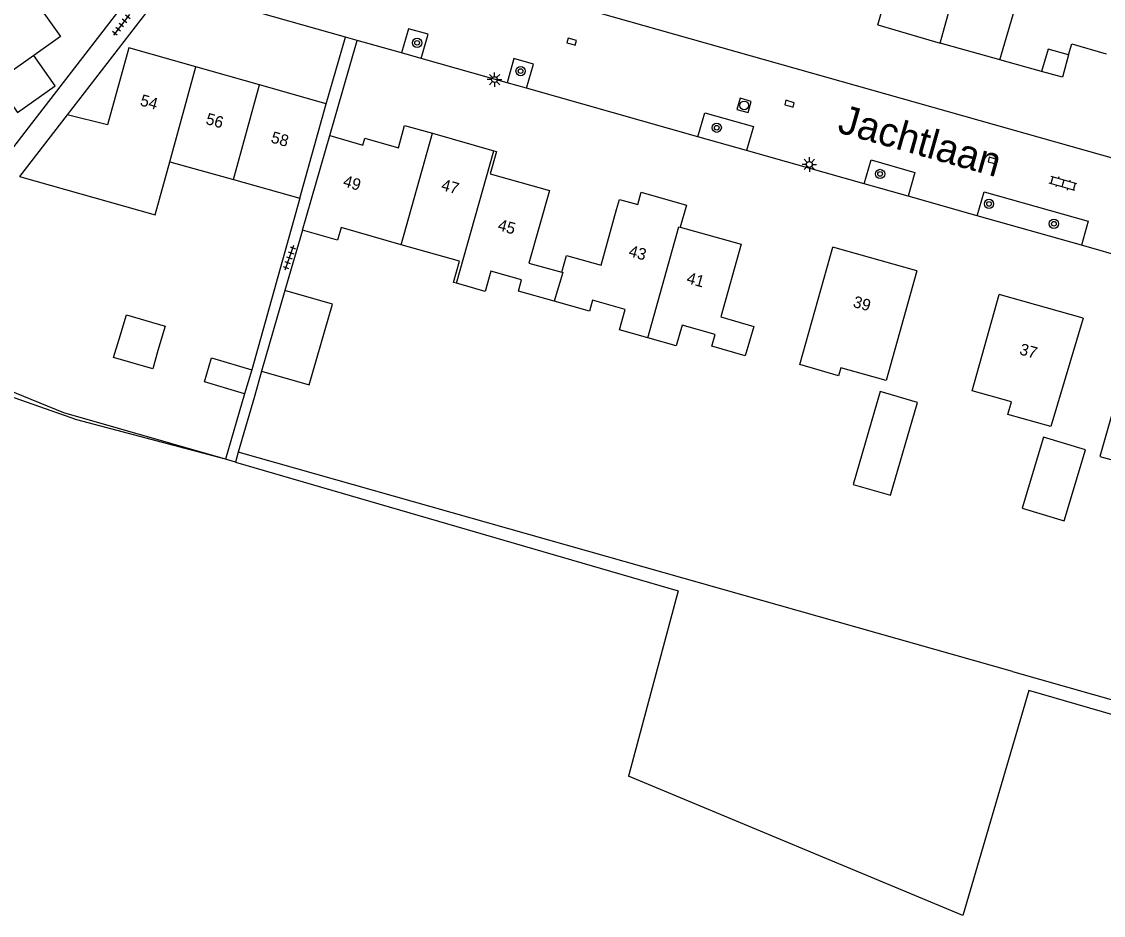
# Model space of a CAD drawing. Extents: x 136000 to 141000, y 400494 to 402006.
# Drawn here: x 137647.9 to 137741.1, y 401598.6 to 401675.6 of the extents above; entities that cross this region are included whole.
import ezdxf

# ---------------------------------------------------------------- set-up
doc = ezdxf.new("R2010")
doc.units = 0
for name, color, linetype in [('gg-afsc-draadraster', 7, 'Continuous'), ('gg-afsc-erfafscheiding', 7, 'Continuous'), ('gg-afsc-lijn draadraster', 7, 'Continuous'), ('gg-anno-huisnummerreeks BGT', 7, 'Continuous'), ('gg-anno-openbare ruimte label', 7, 'Continuous'), ('gg-bbg-gedigitaliseerde bebouwing', 7, 'Continuous'), ('gg-bbg-gedigitaliseerde bijgebouw', 7, 'Continuous'), ('gg-bbg-hoofdgebouw', 7, 'Continuous'), ('gg-bbg-luifel en loopbrug', 7, 'Continuous'), ('gg-bbg-tussenscheiding', 7, 'Continuous'), ('gg-knt-bronhoudergrens', 7, 'Continuous'), ('gg-knt-verharding', 7, 'Continuous'), ('gt-grn-groengrens', 7, 'Continuous'), ('gt-symb-boom', 7, 'Continuous'), ('gt-symb-klinker verharding', 7, 'Continuous'), ('gt-symb-kolk', 7, 'Continuous'), ('gt-symb-lichtmast', 7, 'Continuous'), ('gt-symb-rioolschacht', 7, 'Continuous'), ('gt-symb-tegel verharding', 7, 'Continuous')]:
    doc.layers.add(name, color=color, linetype=linetype)

# ---------------------------------------------------------------- blocks, each defined once
blk = doc.blocks.new('gt0-KOLK')
at = {"layer": 'gt-symb-kolk'}
blk.add_lwpolyline([(0, 0), (0.375, 0), (0.375, 0.4), (-0.375, 0.4), (-0.375, 0), (0, 0)], dxfattribs=at)
blk = doc.blocks.new('gt0-BOOM')
at = {"layer": 'gt-symb-boom'}
for radius in [0.4, 0.2]:
    blk.add_circle((0, 0), radius, dxfattribs=at)
blk = doc.blocks.new('gt0-TEG1')
at = {"layer": 'gt-symb-tegel verharding'}
for p, q in [((-1.125, 0), (1.125, 0)), ((-0.9, -0.25), (-0.9, 0.25)), ((-0.45, -0.25), (-0.45, 0.25)), ((0, -0.25), (0, 0.25)), ((0.45, -0.25), (0.45, 0.25)), ((0.9, -0.25), (0.9, 0.25))]:
    blk.add_line(p, q, dxfattribs=at)
blk = doc.blocks.new('gt0-KL1')
at = {"layer": 'gt-symb-klinker verharding'}
for p, q in [((-1.15, 0.3), (1.15, 0.3)), ((-1, -0.3), (-1, 0.3)), ((-0.5, 0.3), (-0.5, 0.45)), ((0, -0.3), (0, 0.3)), ((0.5, 0.3), (0.5, 0.45)), ((1, -0.3), (1, 0.3)), ((-1.15, -0.3), (1.15, -0.3)), ((-0.5, -0.45), (-0.5, -0.3)), ((0.5, -0.45), (0.5, -0.3))]:
    blk.add_line(p, q, dxfattribs=at)
blk = doc.blocks.new('gt0-RS')
at = {"layer": 'gt-symb-rioolschacht'}
blk.add_lwpolyline([(-0.5, -0.5), (0.5, -0.5), (0.5, 0.5), (-0.5, 0.5)], close=True, dxfattribs=at)
blk.add_circle((0, 0), 0.375, dxfattribs=at)
blk = doc.blocks.new('gt0-LMAST')
at = {"layer": 'gt-symb-lichtmast'}
for p, q in [((-0.182, 0.173), (-0.447, 0.438)), ((-0.005, 0.246), (-0.005, 0.621)), ((0.172, 0.173), (0.437, 0.438)), ((-0.255, -0.004), (-0.63, -0.004)), ((-0.182, -0.181), (-0.447, -0.446)), ((-0.005, -0.254), (-0.005, -0.629)), ((0.437, -0.446), (0.172, -0.181)), ((0.245, -0.004), (0.62, -0.004))]:
    blk.add_line(p, q, dxfattribs=at)
blk.add_circle((-0.005, -0.004), 0.25, dxfattribs=at)

msp = doc.modelspace()

# ---------------------------------------------------------------- linework, layer by layer
at = {"layer": 'gg-afsc-draadraster'}
msp.add_lwpolyline([(137666.316, 401637.686), (137704.484, 401626.586), (137700.203, 401610.62)], dxfattribs=at)
at = {"layer": 'gg-afsc-erfafscheiding'}
for p, q in [((137674.15, 401668.55), (137675.812, 401674.306)), ((137674.44, 401665.82), (137676.809, 401674.024)), ((137671.871, 401660.442), (137667.724, 401645.643)), ((137672.089, 401657.678), (137670.59, 401652.486)), ((137668.578, 401645.521), (137667.95, 401643.347)), ((137667.108, 401643.578), (137665.461, 401637.932)), ((137667.95, 401643.347), (137666.561, 401638.536)), ((137666.561, 401638.536), (137666.316, 401637.686)), ((137666.316, 401637.686), (137665.461, 401637.932))]:
    msp.add_line(p, q, dxfattribs=at)
for points in [[(137645.665, 401659.636), (137644.03, 401660.74), (137648.478, 401666.483)], [(137665.461, 401637.932), (137651.536, 401641.94), (137637.071, 401647.812)]]:
    msp.add_lwpolyline(points, dxfattribs=at)
at = {"layer": 'gg-afsc-lijn draadraster'}
msp.add_lwpolyline([(137666.316, 401637.686), (137704.484, 401626.586), (137700.203, 401610.62)], dxfattribs=at)
at = {"layer": 'gg-bbg-gedigitaliseerde bebouwing'}
for p, q in [((137671.871, 401660.442), (137674.15, 401668.55)), ((137672.089, 401657.678), (137674.44, 401665.82)), ((137659.403, 401658.987), (137660.678, 401663.562)), ((137660.678, 401663.562), (137666.14, 401662.04)), ((137647.723, 401662.308), (137659.403, 401658.987)), ((137666.14, 401662.04), (137671.871, 401660.442)), ((137714.958, 401646.11), (137717.79, 401656.22))]:
    msp.add_line(p, q, dxfattribs=at)
for points in [[(137680.602, 401656.422), (137675.422, 401657.892), (137675.117, 401656.819), (137672.089, 401657.678)], [(137685.368, 401653.097), (137685.098, 401653.174), (137685.616, 401655), (137680.602, 401656.422)], [(137693.771, 401651.561), (137690.712, 401652.429), (137690.982, 401653.379), (137688.327, 401654.133), (137687.834, 401652.398), (137685.368, 401653.097)], [(137725.04, 401654.18), (137722.386, 401644.723), (137718.495, 401645.818)], [(137701.85, 401648.401), (137699.405, 401649.095), (137699.903, 401650.85), (137697.1, 401651.646), (137696.83, 401650.693), (137693.771, 401651.561)], [(137739.38, 401650.1), (137736.592, 401640.763), (137732.882, 401641.802), (137733.188, 401642.896), (137729.804, 401643.843), (137732.13, 401652.13)], [(137710.251, 401646.852), (137707.382, 401647.666), (137707.668, 401648.674), (137704.801, 401649.487), (137704.296, 401647.707), (137701.85, 401648.401)], [(137718.495, 401645.818), (137718.296, 401645.136), (137714.958, 401646.11)], [(137743.149, 401646.411), (137740.815, 401638.186), (137743.952, 401637.296), (137743.961, 401637.331)]]:
    msp.add_lwpolyline(points, dxfattribs=at)
at = {"layer": 'gg-bbg-gedigitaliseerde bijgebouw'}
for p, q in [((137670.59, 401652.486), (137668.578, 401645.521)), ((137660.26, 401649.398), (137659.643, 401647.303)), ((137667.724, 401645.643), (137667.108, 401643.578))]:
    msp.add_line(p, q, dxfattribs=at)
for points in [[(137668.578, 401645.521), (137672.662, 401644.342), (137674.673, 401651.307), (137670.59, 401652.486)], [(137656.302, 401648.287), (137656.919, 401650.382), (137660.26, 401649.398)], [(137659.643, 401647.303), (137659.194, 401645.724), (137655.8, 401646.689), (137656.302, 401648.287)], [(137667.108, 401643.578), (137663.653, 401644.608), (137664.269, 401646.673), (137667.724, 401645.643)], [(137725.087, 401642.835), (137721.867, 401643.765), (137719.557, 401635.768), (137722.777, 401634.838), (137725.087, 401642.835)], [(137739.562, 401638.747), (137735.955, 401639.825), (137734.127, 401633.711), (137737.734, 401632.632), (137739.562, 401638.747)]]:
    msp.add_lwpolyline(points, dxfattribs=at)
at = {"layer": 'gg-bbg-hoofdgebouw'}
for p, q in [((137721.684, 401675.353), (137722.507, 401678.263)), ((137721.684, 401675.353), (137727.056, 401673.786)), ((137732.09, 401672.381), (137727.056, 401673.786)), ((137662.912, 401671.734), (137657.14, 401673.37)), ((137732.194, 401672.352), (137732.09, 401672.381)), ((137735.793, 401671.345), (137732.194, 401672.352)), ((137668.386, 401670.183), (137662.912, 401671.734)), ((137674.15, 401668.55), (137668.386, 401670.183)), ((137651.813, 401667.618), (137647.723, 401662.308)), ((137683.298, 401666.02), (137688.582, 401664.52)), ((137697.834, 401654.654), (137699.167, 401659.465)), ((137725.04, 401654.18), (137717.79, 401656.22)), ((137739.38, 401650.1), (137732.13, 401652.13))]:
    msp.add_line(p, q, dxfattribs=at)
for points in [[(137647.854, 401679.123), (137651.25, 401674.36), (137648.948, 401672.73)], [(137738.119, 401672.775), (137738.398, 401673.735), (137741.341, 401672.879)], [(137648.948, 401672.73), (137645.67, 401670.41), (137647.53, 401667.81)], [(137657.14, 401673.37), (137655.304, 401666.739), (137651.813, 401667.618)], [(137738.119, 401672.775), (137736.346, 401673.259), (137735.793, 401671.345)], [(137674.44, 401665.82), (137677.31, 401665), (137677.48, 401665.59), (137680.37, 401664.76), (137680.9, 401666.7), (137683.298, 401666.02)], [(137688.582, 401664.52), (137688.83, 401664.45), (137688.27, 401662.53), (137693.37, 401661.1), (137691.61, 401654.84), (137694.453, 401654.044)], [(137699.167, 401659.465), (137699.407, 401660.32), (137700.996, 401659.89), (137701.283, 401660.934), (137705.19, 401659.839), (137704.655, 401657.931)], [(137704.655, 401657.931), (137709.89, 401656.47), (137708.14, 401650.21), (137711, 401649.36), (137710.251, 401646.852)], [(137694.453, 401654.044), (137694.857, 401655.481), (137697.834, 401654.654)]]:
    msp.add_lwpolyline(points, dxfattribs=at)
at = {"layer": 'gg-bbg-luifel en loopbrug'}
for points in [[(137647.53, 401667.81), (137650.795, 401670.121), (137648.948, 401672.73)], [(137738.119, 401672.775), (137737.579, 401670.845), (137735.793, 401671.345)]]:
    msp.add_lwpolyline(points, dxfattribs=at)
at = {"layer": 'gg-bbg-tussenscheiding'}
for p, q in [((137732.194, 401672.352), (137735.555, 401683.94)), ((137660.678, 401663.562), (137662.912, 401671.734)), ((137666.14, 401662.04), (137668.386, 401670.183)), ((137680.602, 401656.422), (137683.298, 401666.02)), ((137685.368, 401653.097), (137688.582, 401664.52))]:
    msp.add_line(p, q, dxfattribs=at)
for points in [[(137727.056, 401673.786), (137729.736, 401683.558), (137730.108, 401683.452)], [(137701.85, 401648.401), (137704.531, 401657.966), (137704.655, 401657.931)], [(137694.453, 401654.044), (137694.52, 401654.025), (137693.771, 401651.561)]]:
    msp.add_lwpolyline(points, dxfattribs=at)
at = {"layer": 'gg-knt-bronhoudergrens'}
for points in [[(137665.461, 401637.932), (137652.659, 401641.319), (137633.818, 401647.924), (137625.125, 401652.179)], [(137811.44, 401600.223), (137784.022, 401604.849), (137761.867, 401610.146), (137734.694, 401618.018), (137729.014, 401598.637), (137700.203, 401610.62)]]:
    msp.add_lwpolyline(points, dxfattribs=at)
at = {"layer": 'gg-knt-verharding'}
for p, q in [((137648.478, 401666.483), (137659.075, 401680.201)), ((137660.792, 401679.219), (137651.813, 401667.618)), ((137675.812, 401674.306), (137667.17, 401676.75)), ((137676.809, 401674.024), (137675.812, 401674.306)), ((137680.63, 401672.943), (137676.809, 401674.024)), ((137682.337, 401672.461), (137680.63, 401672.943)), ((137689.732, 401670.369), (137682.337, 401672.461)), ((137691.407, 401669.894), (137689.732, 401670.369)), ((137706.17, 401665.719), (137691.407, 401669.894)), ((137710.363, 401664.533), (137706.17, 401665.719)), ((137720.507, 401661.663), (137710.363, 401664.533)), ((137724.285, 401660.595), (137720.507, 401661.663)), ((137730.249, 401658.908), (137724.285, 401660.595)), ((137739.222, 401656.369), (137730.249, 401658.908)), ((137758.557, 401650.901), (137739.222, 401656.369))]:
    msp.add_line(p, q, dxfattribs=at)
for points in [[(137768.44, 401656.42), (137765.88, 401657.09), (137693.61, 401677.552)], [(137682.337, 401672.461), (137682.927, 401674.546), (137681.22, 401675.03), (137680.63, 401672.943)], [(137691.407, 401669.894), (137691.997, 401671.981), (137690.322, 401672.455), (137689.732, 401670.369)], [(137706.17, 401665.719), (137706.754, 401667.784), (137710.949, 401666.604), (137710.363, 401664.533)], [(137720.507, 401661.663), (137721.089, 401663.721), (137724.867, 401662.65), (137724.285, 401660.595)], [(137730.249, 401658.908), (137730.833, 401660.972), (137739.807, 401658.435), (137739.222, 401656.369)]]:
    msp.add_lwpolyline(points, dxfattribs=at)
at = {"layer": 'gt-grn-groengrens'}
msp.add_line((137733.277, 401619.652), (137666.561, 401638.536), dxfattribs=at)
msp.add_lwpolyline([(137733.277, 401619.652), (137758.874, 401612.375), (137762.395, 401611.486)], dxfattribs=at)

# ---------------------------------------------------------------- block references
at = {"layer": 'gt-symb-boom'}
for p in [(137681.977, 401673.811), (137690.896, 401671.377), (137707.79, 401666.501), (137721.874, 401662.514), (137731.257, 401659.932), (137736.851, 401658.222)]:
    msp.add_blockref('gt0-BOOM', p, dxfattribs=at)
at = {"layer": 'gt-symb-klinker verharding', "rotation": 163.97589033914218}
msp.add_blockref('gt0-KL1', (137737.625, 401661.694), dxfattribs=at)
at = {"layer": 'gt-symb-kolk'}
for p, rotation in [((137695.229, 401673.722), -15.898187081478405), ((137714.009, 401668.375), -15.898187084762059), ((137731.531, 401663.466), -15.898187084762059)]:
    msp.add_blockref('gt0-KOLK', p, dxfattribs=dict(at, rotation=rotation))
at = {"layer": 'gt-symb-lichtmast'}
for p in [(137688.652, 401670.648), (137715.778, 401663.339)]:
    msp.add_blockref('gt0-LMAST', p, dxfattribs=at)
at = {"layer": 'gt-symb-rioolschacht', "rotation": -15.843082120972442}
msp.add_blockref('gt0-RS', (137710.155, 401668.426), dxfattribs=at)
at = {"layer": 'gt-symb-tegel verharding'}
for p, rotation in [((137656.491, 401675.361), -128.01566048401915), ((137670.959, 401655.3), -109.55754166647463)]:
    msp.add_blockref('gt0-TEG1', p, dxfattribs=dict(at, rotation=rotation))

# ---------------------------------------------------------------- texts
at = {"layer": 'gg-anno-huisnummerreeks BGT'}
for s, rotation, p in [('54', 344.2, (137658.032, 401668.44)), ('56', 344.2, (137663.69, 401666.836)), ('58', 344.2, (137669.309, 401665.244)), ('49', 344, (137675.525, 401661.469)), ('47', 344.2, (137683.983, 401661.147)), ('45', 344.3, (137688.857, 401657.693)), ('43', 344.9, (137700.135, 401655.442)), ('41', 344.4, (137705.131, 401653.126)), ('39', 344.3, (137719.466, 401651.074)), ('37', 344.3, (137733.814, 401646.986))]:
    msp.add_text(s, height=1, rotation=rotation, dxfattribs=at).set_placement(p)
at = {"layer": 'gg-anno-openbare ruimte label'}
msp.add_text('Jachtlaan', height=2.5, rotation=344.2, dxfattribs=at).set_placement((137718.1, 401666.13))

doc.saveas('drawing.dxf')
